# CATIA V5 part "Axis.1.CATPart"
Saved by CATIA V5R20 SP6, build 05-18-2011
Part number: Axis.1
Publications: "Point.1", "Line.1", "Line.2", "Line.3"
Bounding box of the stored display mesh (mm): x -20 to 20, y -20 to 20, z -20 to 20
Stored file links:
  C:\Work\#01 CATIA Lecture Materials\#299 TOYOTA CATIA V5\TOYOTA_CATIA\LCS\Surface\Surface EX03\Axis.1.CATPart
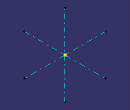
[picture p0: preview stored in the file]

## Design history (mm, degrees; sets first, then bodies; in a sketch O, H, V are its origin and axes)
Set1 "Axis"
  Point1: stored without definition
  Line1 to Line3: stored without definition
Body1 (main body)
